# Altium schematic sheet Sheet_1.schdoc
size 596 x 220 mm
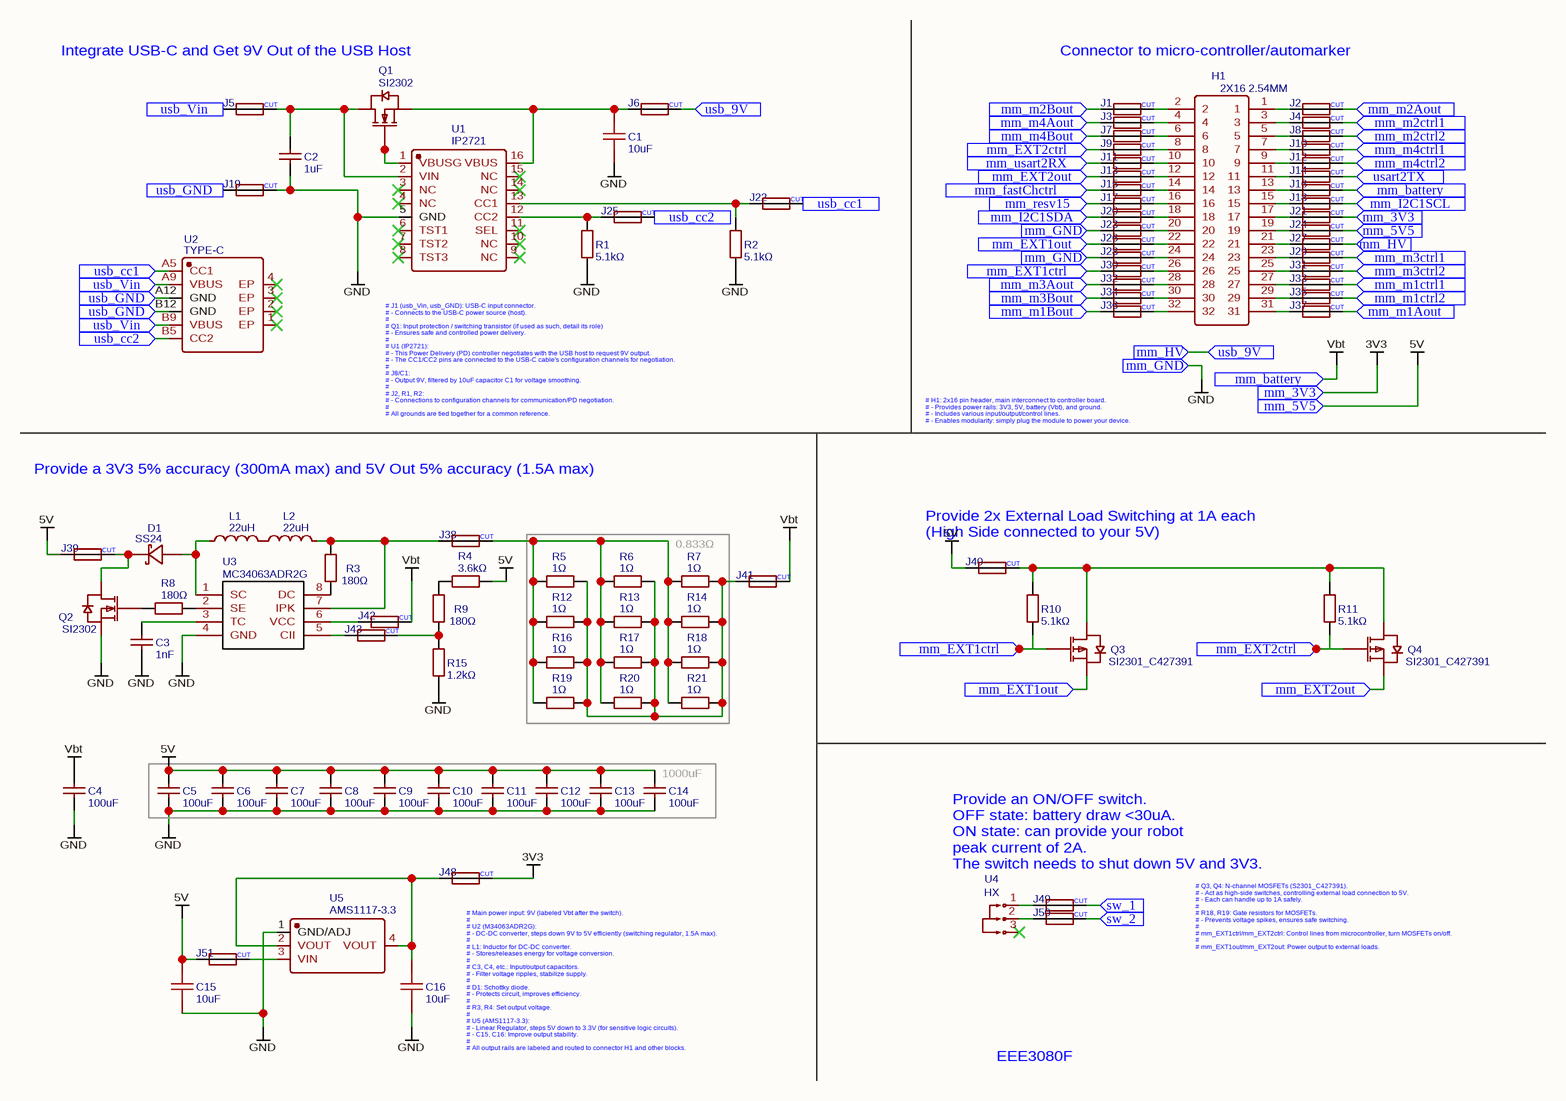
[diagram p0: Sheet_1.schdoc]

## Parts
C1  10uF  [C0805]
C2  1uF  [C0805]
C3  1nF  [C0805]
C4  100uF  [C1206]
C5  100uF  [C1206]
C6  100uF  [C1206]
C7  100uF  [C1206]
C8  100uF  [C1206]
C9  100uF  [C1206]
C10  100uF  [C1206]
C11  100uF  [C1206]
C12  100uF  [C1206]
C13  100uF  [C1206]
C14  100uF  [C1206]
C15  10uF  [C0805]
C16  10uF  [C0805]
D1  SS24  [SMA_L4.3-W2.6-LS5.0-FD]
H1  2X16 2.54MM  [DIP-2X16P-2.54MM]
J1  0603  [JMP-0603-CUTTABLE]  (value not drawn)
J2  0603  [JMP-0603-CUTTABLE]  (value not drawn)
J3  0603  [JMP-0603-CUTTABLE]  (value not drawn)
J4  0603  [JMP-0603-CUTTABLE]  (value not drawn)
J5  0603  [JMP-0603-CUTTABLE]  (value not drawn)
J6  0603  [JMP-0603-CUTTABLE]  (value not drawn)
J7  0603  [JMP-0603-CUTTABLE]  (value not drawn)
J8  0603  [JMP-0603-CUTTABLE]  (value not drawn)
J9  0603  [JMP-0603-CUTTABLE]  (value not drawn)
J10  0603  [JMP-0603-CUTTABLE]  (value not drawn)
J11  0603  [JMP-0603-CUTTABLE]  (value not drawn)
J12  0603  [JMP-0603-CUTTABLE]  (value not drawn)
J13  0603  [JMP-0603-CUTTABLE]  (value not drawn)
J14  0603  [JMP-0603-CUTTABLE]  (value not drawn)
J15  0603  [JMP-0603-CUTTABLE]  (value not drawn)
J16  0603  [JMP-0603-CUTTABLE]  (value not drawn)
J17  0603  [JMP-0603-CUTTABLE]  (value not drawn)
J18  0603  [JMP-0603-CUTTABLE]  (value not drawn)
J19  0603  [JMP-0603-CUTTABLE]  (value not drawn)
J20  0603  [JMP-0603-CUTTABLE]  (value not drawn)
J21  0603  [JMP-0603-CUTTABLE]  (value not drawn)
J22  0603  [JMP-0603-CUTTABLE]  (value not drawn)
J23  0603  [JMP-0603-CUTTABLE]  (value not drawn)
J24  0603  [JMP-0603-CUTTABLE]  (value not drawn)
J25  0603  [JMP-0603-CUTTABLE]  (value not drawn)
J26  0603  [JMP-0603-CUTTABLE]  (value not drawn)
J27  0603  [JMP-0603-CUTTABLE]  (value not drawn)
J28  0603  [JMP-0603-CUTTABLE]  (value not drawn)
J29  0603  [JMP-0603-CUTTABLE]  (value not drawn)
J30  0603  [JMP-0603-CUTTABLE]  (value not drawn)
J31  0603  [JMP-0603-CUTTABLE]  (value not drawn)
J32  0603  [JMP-0603-CUTTABLE]  (value not drawn)
J33  0603  [JMP-0603-CUTTABLE]  (value not drawn)
J34  0603  [JMP-0603-CUTTABLE]  (value not drawn)
J35  0603  [JMP-0603-CUTTABLE]  (value not drawn)
J36  0603  [JMP-0603-CUTTABLE]  (value not drawn)
J37  0603  [JMP-0603-CUTTABLE]  (value not drawn)
J38  0603  [JMP-0603-CUTTABLE]  (value not drawn)
J39  0603  [JMP-0603-CUTTABLE]  (value not drawn)
J40  0603  [JMP-0603-CUTTABLE]  (value not drawn)
J41  0603  [JMP-0603-CUTTABLE]  (value not drawn)
J42  0603  [JMP-0603-CUTTABLE]  (value not drawn)
J43  0603  [JMP-0603-CUTTABLE]  (value not drawn)
J48  0603  [JMP-0603-CUTTABLE]  (value not drawn)
J49  0603  [JMP-0603-CUTTABLE]  (value not drawn)
J50  0603  [JMP-0603-CUTTABLE]  (value not drawn)
J51  0603  [JMP-0603-CUTTABLE]  (value not drawn)
L1  22uH  [IND-SMD_L12.5-W12.5]
L2  22uH  [IND-SMD_L12.5-W12.5]
Q1  SI2302  [SOT-23-3_L2.9-W1.3-P1.90-LS2.4-BR]
Q2  SI2302  [SOT-23-3_L2.9-W1.3-P1.90-LS2.4-BR]
Q3  SI2301_C427391  [SOT-23-3_L2.9-W1.5-P1.90-LS2.6-BL]
Q4  SI2301_C427391  [SOT-23-3_L2.9-W1.5-P1.90-LS2.6-BL]
R1  5.1kΩ  [R0805]
R2  5.1kΩ  [R0805]
R3  180Ω  [R0805]
R4  3.6kΩ  [R0805]
R5  1Ω  [R0805]
R6  1Ω  [R0805]
R7  1Ω  [R0805]
R8  180Ω  [R0805]
R9  180Ω  [R0805]
R10  5.1kΩ  [R0805]
R11  5.1kΩ  [R0805]
R12  1Ω  [R0805]
R13  1Ω  [R0805]
R14  1Ω  [R0805]
R15  1.2kΩ  [R0805]
R16  1Ω  [R0805]
R17  1Ω  [R0805]
R18  1Ω  [R0805]
R19  1Ω  [R0805]
R20  1Ω  [R0805]
R21  1Ω  [R0805]
U1  IP2721  [TSSOP-16_L5.0-W4.4-P0.65-LS6.4-BL]
U2  TYPE-C  [USB-C-SMD_HC-TYPE-C-6P-010B]
U3  MC34063ADR2G  [SOIC-8_L5.0-W4.0-P1.27-LS6.0-BL]
U4  HX  [SW-TH_3P-P4.80-HX-SS12D10G4]
U5  AMS1117-3.3  [SOT-223-3_L6.5-W3.4-P2.30-LS7.0-BR]

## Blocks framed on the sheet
0.833Ω: R5-R7 R12-R14 R16-R21
1000uF: C5-C14

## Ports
mm_3V3 (in), mm_5V5 (in), mm_battery (in), mm_EXT1ctrl (in), mm_EXT1out (in), mm_EXT2ctrl (in), mm_EXT2out (in), mm_fastChctrl (in), mm_GND (in), mm_HV (in), mm_I2C1SCL (in), mm_I2C1SDA (in), mm_m1Aout (in), mm_m1Bout (in), mm_m1ctrl1 (in), mm_m1ctrl2 (in), mm_m2Aout (in), mm_m2Bout (in), mm_m2ctrl1 (in), mm_m2ctrl2 (in), mm_m3Aout (in), mm_m3Bout (in), mm_m3ctrl1 (in), mm_m3ctrl2 (in), mm_m4Aout (in), mm_m4Bout (in), mm_m4ctrl1 (in), mm_m4ctrl2 (in), mm_resv15 (in), mm_usart2RX (in), sw_1 (in), sw_2 (in), usart2TX (in), usb_9V (in), usb_cc1 (in), usb_cc2 (in), usb_GND (in), usb_Vin (in)

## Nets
3V3: J21.1 J48.1 ; port mm_3V3
5V: C5.2 C6.2 C7.2 C8.2 C9.2 C10.2 C11.2 C12.2 C13.2 C14.2 C15.1 J24.1 J39.2 J40.2 J51.2 R4.1 ; port mm_5V5
GND: C1.2 C2.2 C3.1 C4.1 C5.1 C6.1 C7.1 C8.1 C9.1 C10.1 C11.1 C12.1 C13.1 C14.1 C15.2 C16.2 J19.1 J23.2 J28.2 Q2.2(S) R1.2 R2.2 R15.2 U1.5(GND) U3.4(GND) U5.1(GND/ADJ) ; port mm_GND
Vbt: C4.2 J16.1 J41.1 J42.1 ; port mm_battery
mm_EXT1ctrl: J30.2 Q3.1(G) R10.2 ; port mm_EXT1ctrl
mm_EXT1out: J26.2 Q3.2(S) ; port mm_EXT1out
mm_EXT2ctrl: J9.2 Q4.1(G) R11.2 ; port mm_EXT2ctrl
mm_EXT2out: J13.2 Q4.2(S) ; port mm_EXT2out
mm_fastChctrl: J15.2 ; port mm_fastChctrl
mm_HV: J6.1 J27.1 ; port usb_9V, port mm_HV
mm_I2C1SCL: J18.1 ; port mm_I2C1SCL
mm_I2C1SDA: J20.2 ; port mm_I2C1SDA
mm_m1Aout: J37.1 ; port mm_m1Aout
mm_m1Bout: J36.2 ; port mm_m1Bout
mm_m1ctrl1: J33.1 ; port mm_m1ctrl1
mm_m1ctrl2: J35.1 ; port mm_m1ctrl2
mm_m2Aout: J2.1 ; port mm_m2Aout
mm_m2Bout: J1.2 ; port mm_m2Bout
mm_m2ctrl1: J4.1 ; port mm_m2ctrl1
mm_m2ctrl2: J8.1 ; port mm_m2ctrl2
mm_m3Aout: J32.2 ; port mm_m3Aout
mm_m3Bout: J34.2 ; port mm_m3Bout
mm_m3ctrl1: J29.1 ; port mm_m3ctrl1
mm_m3ctrl2: J31.1 ; port mm_m3ctrl2
mm_m4Aout: J3.2 ; port mm_m4Aout
mm_m4Bout: J7.2 ; port mm_m4Bout
mm_m4ctrl1: J10.1 ; port mm_m4ctrl1
mm_m4ctrl2: J12.1 ; port mm_m4ctrl2
mm_resv15: J17.2 ; port mm_resv15
mm_usart2RX: J11.2 ; port mm_usart2RX
sw_1: J49.1 ; port sw_1
sw_2: J50.1 ; port sw_2
usart2TX: J14.1 ; port usart2TX
usb_cc1: J22.1 U2.A5(CC1) ; port usb_cc1
usb_cc2: J25.1 U2.B5(CC2) ; port usb_cc2
usb_GND: J19.2 U2.A12(GND) U2.B12(GND) ; port usb_GND
usb_Vin: J5.2 U2.A9(VBUS) U2.B9(VBUS) ; port usb_Vin
NetC1_1: C1.1 J6.2 Q1.2(S) U1.16(VBUS)
NetC2_1: C2.1 J5.1 Q1.3(D) U1.2(VIN)
NetC3_2: C3.2 U3.3(TC)
NetC16_1: C16.1 J48.2 U5.2(VOUT) U5.4(VOUT)
NetD1_1: D1.1(A) L1.1 U3.1(SC)
NetD1_2: D1.2(K) J39.1 Q2.3(D)
NetH1_1: H1.1 J2.2
NetH1_2: H1.2 J1.1
NetH1_3: H1.3 J4.2
NetH1_4: H1.4 J3.1
NetH1_5: H1.5 J8.2
NetH1_6: H1.6 J7.1
NetH1_7: H1.7 J10.2
NetH1_8: H1.8 J9.1
NetH1_9: H1.9 J12.2
NetH1_10: H1.10 J11.1
NetH1_11: H1.11 J14.2
NetH1_12: H1.12 J13.1
NetH1_13: H1.13 J16.2
NetH1_14: H1.14 J15.1
NetH1_15: H1.15 J18.2
NetH1_16: H1.16 J17.1
NetH1_17: H1.17 J21.2
NetH1_18: H1.18 J20.1
NetH1_19: H1.19 J24.2
NetH1_20: H1.20 J23.1
NetH1_21: H1.21 J27.2
NetH1_22: H1.22 J26.1
NetH1_23: H1.23 J29.2
NetH1_24: H1.24 J28.1
NetH1_25: H1.25 J31.2
NetH1_26: H1.26 J30.1
NetH1_27: H1.27 J33.2
NetH1_28: H1.28 J32.1
NetH1_29: H1.29 J35.2
NetH1_30: H1.30 J34.1
NetH1_31: H1.31 J37.2
NetH1_32: H1.32 J36.1
NetJ22_2: J22.2 R2.1 U1.13(CC1)
NetJ25_2: J25.2 R1.1 U1.12(CC2)
NetJ38_1: J38.1 R5.1 R6.1 R7.1 R12.1 R13.1 R14.1 R16.1 R17.1 R18.1 R19.1 R20.1 R21.1
NetJ38_2: J38.2 L2.2 R3.1 U3.7(IPK)
NetJ40_1: J40.1 Q3.3(D) Q4.3(D) R10.1 R11.1
NetJ41_2: J41.2 R5.2 R6.2 R7.2 R12.2 R13.2 R14.2 R16.2 R17.2 R18.2 R19.2 R20.2 R21.2
NetJ42_2: J42.2 U3.6(VCC)
NetJ43_1: J43.1 R9.2 R15.1
NetJ43_2: J43.2 U3.5(CII)
NetJ49_2: J49.2 U4.1
NetJ50_2: J50.2 U4.2
NetJ51_1: J51.1 U5.3(VIN)
NetL1_2: L1.2 L2.1
NetQ1_1: Q1.1(G) U1.1(VBUSG)
NetQ2_1: Q2.1(G) R8.1
NetR3_2: R3.2 U3.8(DC)
NetR4_2: R4.2 R9.1
NetR8_2: R8.2 U3.2(SE)

Not connected (* = marked no-connect by the designer): U1 3(NC)* 4(NC)* 6(TST1)* 7(TST2)* 8(TST3)* 9(NC)* 10(NC)* 11(SEL)* 14(NC)* 15(NC)*; U2 1(EP)* 2(EP)* 3(EP)* 4(EP)*; U4 3*

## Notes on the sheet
- Integrate USB-C and Get 9V Out of the USB Host
- Connector to micro-controller/automarker
- (near U1) # J1 (usb_Vin, usb_GND): USB-C input connector.
  # - Connects to the USB-C power source (host).
  #
  # Q1: Input protection / switching transistor (if used as such, detail its role)
  # - Ensures safe and controlled power delivery.
  #
  # U1 (IP2721):
  # - This Power Delivery (PD) controller negotiates with the USB host to request 9V output.
  # - The CC1/CC2 pins are connected to the USB-C cable's configuration channels for negotiation.
  #
  # J8/C1:
  # - Output 9V, filtered by 10uF capacitor C1 for voltage smoothing.
  #
  # J2, R1, R2:
  # - Connections to configuration channels for communication/PD negotiation.
  #
  # All grounds are tied together for a common reference.
- (near J40) # H1: 2x16 pin header, main interconnect to controller board.
  # - Provides power rails: 3V3, 5V, battery (Vbt), and ground.
  # - Includes various input/output/control lines.
  # - Enables modularity: simply plug the module to power your device.
- Provide a 3V3 5% accuracy (300mA max) and 5V Out 5% accuracy (1.5A max)
- Provide 2x External Load Switching at 1A each
  (High Side connected to your 5V)
- Provide an ON/OFF switch.
  OFF state: battery draw <30uA.
  ON state: can provide your robot
  peak current of 2A.
  The switch needs to shut down 5V and 3V3.
- # Q3, Q4: N-channel MOSFETs (S2301_C427391).
  # - Act as high-side switches, controlling external load connection to 5V.
  # - Each can handle up to 1A safely.
  #
  # R18, R19: Gate resistors for MOSFETs.
  # - Prevents voltage spikes, ensures safe switching.
  #
  # mm_EXT1ctrl/mm_EXT2ctrl: Control lines from microcontroller, turn MOSFETs on/off.
  #
  # mm_EXT1out/mm_EXT2out: Power output to external loads.
- (near J48) # Main power input: 9V (labeled Vbt after the switch).
  #
  # U2 (M34063ADR2G):
  # - DC-DC converter, steps down 9V to 5V efficiently (switching regulator, 1.5A max).
  #
  # L1: Inductor for DC-DC converter.
  # - Stores/releases energy for voltage conversion.
  #
  # C3, C4, etc.: Input/output capacitors.
  # - Filter voltage ripples, stabilize supply.
  #
  # D1: Schottky diode.
  # - Protects circuit, improves efficiency.
  #
  # R3, R4: Set output voltage.
  #
  # U5 (AMS1117-3.3):
  # - Linear Regulator, steps 5V down to 3.3V (for sensitive logic circuits).
  # - C15, C16: Improve output stability.
  #
  # All output rails are labeled and routed to connector H1 and other blocks.
- EEE3080F

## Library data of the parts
C1 C15 C16 = 10uF: Manufacturer: SAMSUNG(三星); nameAlias: Value
C2 = 1uF: Manufacturer: SAMSUNG(三星); nameAlias: Value
C3 = 1nF: Manufacturer: SAMSUNG(三星); nameAlias: Value
C4-C14 = 100uF: Manufacturer: SAMSUNG(三星); nameAlias: Value
D1 = SS24: Manufacturer: 宏迦橙; Contributor: lcsc
H1 = 2X16 2.54MM: Manufacturer: CONNFLY; Manufacturer Part: DS1023-2*16SF11; Contributor: HAIIM
J1-J43 J48-J51 = 0603: Manufacturer: Tim Hosking; Contributor: MisterJan
L1 L2 = 22uH: Manufacturer: SXN(顺翔诺); nameAlias: Value; Contributor: lcsc
Q1 Q2 = SI2302: Manufacturer: MDD(辰达半导体); Contributor: LCSC
Q3 Q4 = SI2301_C427391: Manufacturer: MDD(辰达半导体); Manufacturer Part: MDD2301; Contributor: LCSC
R1 R2 R10 R11 = 5.1kΩ: Manufacturer: UNI-ROYAL(厚声); nameAlias: Value
R3 R8 R9 = 180Ω: Manufacturer: UNI-ROYAL(厚声); nameAlias: Value
R4 = 3.6kΩ: Manufacturer: UNI-ROYAL(厚声); nameAlias: Value
R5-R7 R12-R14 R16-R21 = 1Ω: Manufacturer: UNI-ROYAL(厚声); nameAlias: Value
R15 = 1.2kΩ: Manufacturer: UNI-ROYAL(厚声); nameAlias: Value
U1 = IP2721: Manufacturer: INJOINIC(英集芯); Contributor: LCSC
U2 = TYPE-C: Manufacturer: HC(虹成电子); Manufacturer Part: HC-TYPE-C-6P-010C; Contributor: lcsc
U3 = MC34063ADR2G: Manufacturer: onsemi(安森美)
U4 = HX: Manufacturer: hanxia(韩下); Manufacturer Part: HX SS12D10G6; Contributor: lcsc
U5 = AMS1117-3.3: Manufacturer: AMS; sourceId: dwIGgezVh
